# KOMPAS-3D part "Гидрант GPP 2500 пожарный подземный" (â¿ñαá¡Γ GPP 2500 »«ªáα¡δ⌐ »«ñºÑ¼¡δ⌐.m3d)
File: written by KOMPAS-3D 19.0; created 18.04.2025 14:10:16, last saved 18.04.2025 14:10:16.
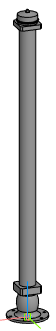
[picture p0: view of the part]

Document properties: Полное имя файла: E:\Dendor Работа Сачек\3D для проекитирвщиков\11.1 Тип GPP. Гидрант пожарный подземный\stp_Тип GPP. 750-6000 Гидрант пожарный подземный\Гидрант GPP 2500 пожарный подземный.m3d

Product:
- Part/product: Гидрант GPP 2500 пожарный подземный

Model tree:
1. Операция без истории:1  (labels: Гидрант GPP 2500 пожарный подземный)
